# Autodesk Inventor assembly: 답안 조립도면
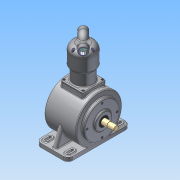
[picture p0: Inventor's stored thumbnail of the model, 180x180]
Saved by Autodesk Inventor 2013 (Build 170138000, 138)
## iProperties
Created: 2015-06
Part Number: 답안 조립도면
Document SubType Name: Assembly
Designer: dgall
Author: dgall
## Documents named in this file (15)
- C:\Documents and Settings\dgall\바탕 화면\450605V1014\답안 조립도면.iam
- C:\Documents and Settings\dgall\바탕 화면\450605V1014\본체.ipt
- C:\Documents and Settings\dgall\바탕 화면\450605V1014\실린더.ipt
- C:\Documents and Settings\dgall\바탕 화면\450605V1014\실린더헤드.ipt
- C:\Documents and Settings\dgall\바탕 화면\450605V1014\메인커버.ipt
- C:\Documents and Settings\dgall\바탕 화면\450605V1014\메인 크랭크 축-구동부.ipt
- C:\Documents and Settings\dgall\바탕 화면\450605V1014\크랭크 서브축.ipt
- C:\Documents and Settings\dgall\바탕 화면\450605V1014\커넥팅 로드.ipt
- C:\Documents and Settings\dgall\바탕 화면\450605V1014\피스톤.ipt
- C:\Documents and Settings\dgall\바탕 화면\450605V1014\피스톤 핀.ipt
- C:\Documents and Settings\dgall\바탕 화면\450605V1014\베어링 6204.ipt
- C:\Documents and Settings\dgall\바탕 화면\450605V1014\베어링 NA 4902.ipt
- C:\Documents and Settings\dgall\바탕 화면\450605V1014\오일실.ipt
- C:\Documents and Settings\dgall\바탕 화면\450605V1014\M5x0.8.ipt
- C:\Documents and Settings\dgall\바탕 화면\450605V1014\M4x0.7.ipt
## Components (14 placed, 4 different names)
1. 피스톤:1
2. 피스톤 핀:1
3. M5x0.8:1
4. M5x0.8:2
5. M5x0.8:3
6. M5x0.8:4
7. M4x0.7:1
8. M4x0.7:2
9. M4x0.7:3
10. M4x0.7:4
11. M4x0.7:5
12. M4x0.7:6
13. M4x0.7:7
14. M4x0.7:8
